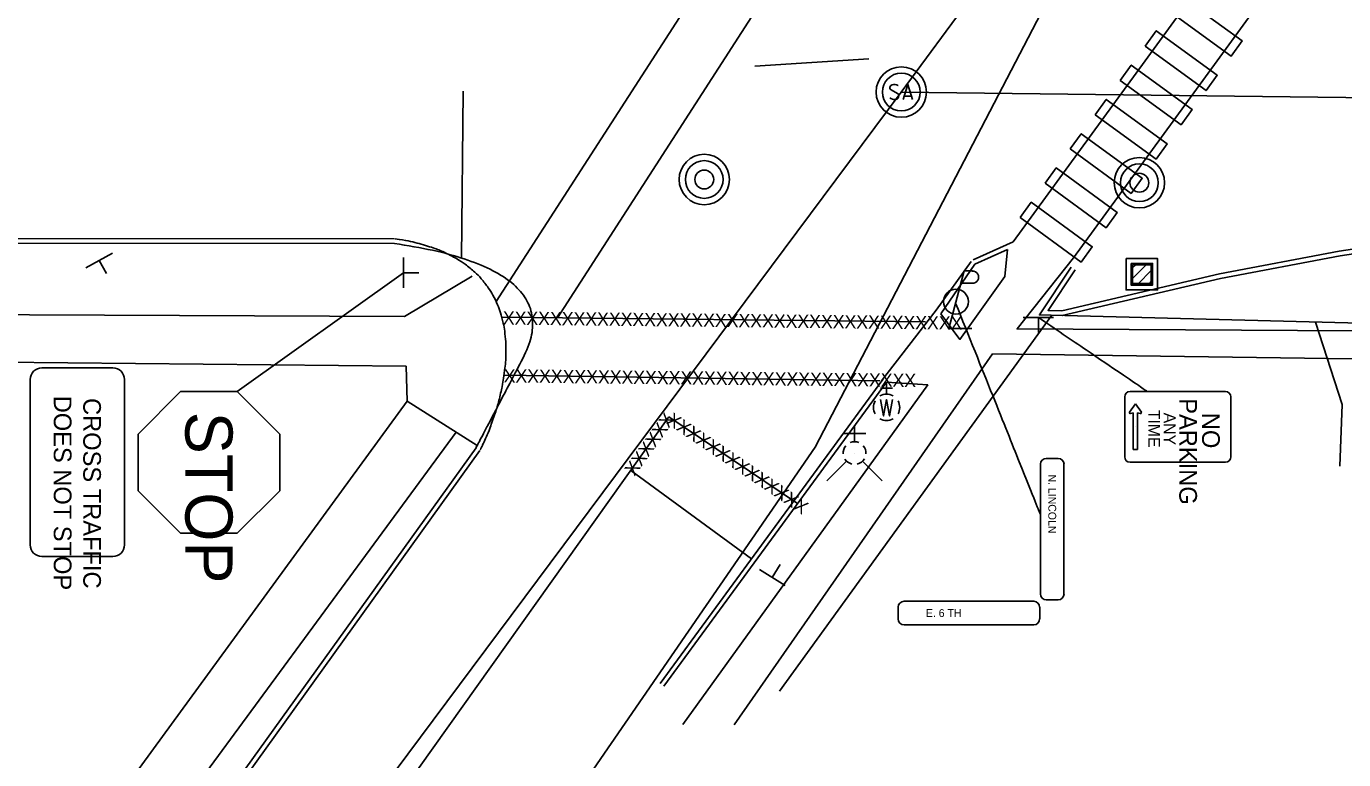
# Model space of a CAD drawing. Extents: x 108269 to 109415, y 548506 to 548874.
# Drawn here: x 108929.7 to 109069.3, y 548635.6 to 548713.3 of the extents above; entities that cross this region are included whole.
import ezdxf

# ---------------------------------------------------------------- set-up
doc = ezdxf.new("R2010")
doc.units = 0
for name, color, linetype in [('Default', 7, 'Continuous'), ('PM_P_Crosswalk', 7, 'Continuous'), ('PM_P_Removal', 7, 'Continuous'), ('PM_P_Stop_Line', 7, 'Continuous'), ('SH_Data', 7, 'Continuous'), ('SH_Text', 7, 'Continuous'), ('SN_P_Post', 7, 'Continuous'), ('SN_P_Signs', 7, 'Continuous'), ('SN_P_Text', 7, 'Continuous'), ('SN_X_Post', 7, 'Continuous'), ('SN_X_Public', 7, 'Continuous')]:
    doc.layers.add(name, color=color, linetype=linetype)

msp = doc.modelspace()

# ---------------------------------------------------------------- linework, layer by layer
at = {"layer": 'Default'}
for p, q in [((109022.45, 548706.36), (109144.06, 548871.47)), ((109013.34, 548668.7), (109047.97, 548735.38)), ((109062.3, 548728.89), (109034.32, 548690.49)), ((109069.3, 548728.02), (109040.71, 548688.79)), ((109002.56, 548719.87), (108979.51, 548684.16)), ((109010.93, 548721.11), (108986.03, 548682.43)), ((109022.45, 548708.36), (109022.45, 548708.36)), ((108875.3, 548508.88), (109022.45, 548706.36)), ((108976.03, 548706.46), (108975.84, 548688.73)), ((109022.45, 548706.36), (109022.45, 548706.36)), ((109022.45, 548706.36), (109022.45, 548706.36)), ((109022.45, 548706.36), (109022.45, 548706.36)), ((109022.45, 548706.36), (109415.28, 548701.66)), ((109022.45, 548704.36), (109022.45, 548704.36)), ((109001.57, 548699.09), (109001.57, 548699.09)), ((109047.68, 548698.75), (109047.68, 548698.75)), ((109001.57, 548697.09), (109001.57, 548697.09)), ((109001.57, 548697.09), (109001.57, 548697.09)), ((109001.57, 548697.09), (109001.57, 548697.09)), ((109047.68, 548696.75), (109047.68, 548696.75)), ((109047.68, 548696.75), (109047.68, 548696.75)), ((109047.68, 548696.75), (109047.68, 548696.75)), ((109001.57, 548695.09), (109001.57, 548695.09)), ((109047.68, 548694.75), (109047.68, 548694.75)), ((108913.18, 548690.84), (108968.76, 548690.81)), ((108913.18, 548690.34), (108968.75, 548690.31)), ((109030.06, 548688.58), (109034.32, 548690.49)), ((109030.26, 548688.12), (109033.71, 548689.66)), ((109026.15, 548683.23), (109029.85, 548688.4)), ((109026.65, 548682.86), (109030.26, 548688.12)), ((109046.8, 548686.44), (109048.56, 548688.19)), ((109046.8, 548687.57), (109047.43, 548688.19)), ((109047.94, 548688.71), (109047.94, 548688.71)), ((109047.94, 548688.05), (109047.94, 548688.05)), ((109029.11, 548687.39), (109029.98, 548687.39)), ((109046.94, 548687.05), (109046.94, 548687.05)), ((109047.4, 548685.9), (109049.09, 548687.6)), ((109047.94, 548687.05), (109047.94, 548687.05)), ((109047.94, 548687.05), (109047.94, 548687.05)), ((109047.94, 548687.05), (109047.94, 548687.05)), ((109048.53, 548685.9), (109049.09, 548686.46)), ((109048.94, 548687.05), (109048.94, 548687.05)), ((109028.77, 548686.09), (109029.98, 548686.09)), ((109047.94, 548686.05), (109047.94, 548686.05)), ((109047.94, 548685.38), (109047.94, 548685.38)), ((108980.11, 548682.5), (109025.03, 548681.99)), ((109009.53, 548642.86), (109038.39, 548682.7)), ((109020.37, 548675.75), (109026.15, 548683.23)), ((109038.39, 548682.7), (109082.29, 548681.55)), ((108980.36, 548676.36), (109020.17, 548675.75)), ((108996.9, 548643.67), (109020.48, 548675.9)), ((108997.3, 548643.38), (109020.89, 548675.6)), ((109020.89, 548674.33), (109020.89, 548675.6)), ((109021.52, 548674.97), (109020.25, 548674.97)), ((108911.44, 548593.24), (108970.1, 548673.58)), ((109020.89, 548672.93), (109020.89, 548672.93)), ((108997.83, 548671.92), (108931.45, 548578.74)), ((108997.83, 548671.92), (109011.46, 548662.73)), ((109017.5, 548669.29), (109017.5, 548671.01)), ((108916.2, 548589.93), (108975.28, 548670.32)), ((109018.7, 548670.15), (109016.3, 548670.15)), ((108977.39, 548668.66), (108921.03, 548590.17)), ((108977.8, 548668.37), (108921.44, 548589.88)), ((108930.39, 548548.27), (109013.34, 548668.7)), ((109016.65, 548667.24), (109014.57, 548665.16)), ((109017.5, 548668.09), (109017.5, 548668.09)), ((109017.5, 548668.09), (109017.5, 548668.09)), ((109018.35, 548667.24), (109020.43, 548665.16))]:
    msp.add_line(p, q, dxfattribs=at)
for points in [[(109022.11, 548707.05), (109022.09, 548707.07), (109022.05, 548707.1), (109021.94, 548707.14), (109021.8, 548707.16), (109021.7, 548707.16), (109021.66, 548707.16), (109021.5, 548707.12), (109021.36, 548707.05), (109021.27, 548706.95), (109021.25, 548706.85), (109021.25, 548706.77), (109021.27, 548706.67), (109021.37, 548706.58), (109022.06, 548706.21), (109022.13, 548706.16), (109022.15, 548706.1), (109022.18, 548706.03), (109022.18, 548705.95), (109022.16, 548705.88), (109022.15, 548705.83), (109022.13, 548705.76), (109022.1, 548705.71), (109022.08, 548705.68), (109022.04, 548705.64), (109022, 548705.61), (109021.95, 548705.59), (109021.91, 548705.58), (109021.8, 548705.56), (109021.62, 548705.56), (109021.51, 548705.59), (109021.35, 548705.68), (109021.25, 548705.75)], [(109022.66, 548705.56), (109023.16, 548707.16), (109023.65, 548705.56)], [(109023.53, 548705.94), (109022.78, 548705.94)], [(109089.48, 548690.87), (109079.37, 548690.91), (109075.22, 548690.46), (109068.87, 548689.49), (109056.19, 548687.1), (109039.46, 548683.17), (109038, 548683.21), (109040.86, 548687.51)], [(109026.65, 548682.86), (109028.67, 548680.13), (109033.41, 548686.79), (109033.71, 548689.66)], [(109040.44, 548687.78), (109037.09, 548682.73), (109039.51, 548682.67), (109056.29, 548686.61), (109068.96, 548688.99), (109075.29, 548689.96), (109079.4, 548690.41), (109089.48, 548690.37)], [(109094.15, 548680.9), (109034.73, 548681.25), (109040.71, 548688.79)], [(108898.24, 548682.87), (108969.79, 548682.57), (108976.97, 548686.84)], [(109029.11, 548687.39), (109027.48, 548681.29), (109029.92, 548681.29)], [(109066.33, 548681.97), (109069.16, 548673.22), (109068.91, 548666.69)], [(108898.23, 548677.99), (108969.97, 548677.3), (108970.1, 548673.58), (108977.51, 548668.9)], [(109169.39, 548676.69), (109032.13, 548678.6), (109004.75, 548639.27)], [(108999.31, 548639.32), (109025.26, 548675.31), (109020.89, 548675.6)], [(109020.25, 548673.75), (109020.57, 548672.03), (109020.89, 548673.75), (109021.21, 548672.03), (109021.52, 548673.75)]]:
    msp.add_lwpolyline(points, dxfattribs=at)
for points in [[(109046.28, 548688.71), (109049.61, 548688.71), (109049.61, 548685.38), (109046.28, 548685.38)], [(109046.8, 548688.19), (109049.09, 548688.19), (109049.09, 548685.9), (109046.8, 548685.9)], [(109046.94, 548688.05), (109048.94, 548688.05), (109048.94, 548686.05), (109046.94, 548686.05)]]:
    msp.add_lwpolyline(points, close=True, dxfattribs=at)
for centre, radius in [((109022.45, 548706.36), 2.67), ((109022.45, 548706.36), 2), ((109022.45, 548706.36), 2), ((109001.57, 548697.09), 2.67), ((109001.57, 548697.09), 2), ((109001.57, 548697.09), 2), ((109047.68, 548696.75), 2.67), ((109001.57, 548697.09), 1), ((109047.68, 548696.75), 2), ((109047.68, 548696.75), 2), ((109047.68, 548696.75), 1), ((109028.24, 548684.14), 1.32)]:
    msp.add_circle(centre, radius, dxfattribs=at)
for centre, radius, start, end in [((109029.99, 548686.74), 0.648, 268.8767, 91.1233), ((109020.89, 548672.93), 1.4, 60.0184, 120.0157), ((109020.89, 548672.93), 1.4, 150.0184, 209.9816), ((109020.89, 548672.93), 1.4, 330.0184, 29.9816), ((109020.89, 548672.93), 1.4, 239.9843, 299.9816), ((109017.5, 548668.09), 1.2, 140.021, 184.0629), ((109017.5, 548668.09), 1.2, 68.1395, 112.038), ((109017.5, 548668.09), 1.2, 356.0165, 39.9889), ((109017.5, 548668.09), 1.2, 211.8788, 255.8479), ((109017.5, 548668.09), 1.2, 283.8239, 329.9097)]:
    msp.add_arc(centre, radius, start, end, dxfattribs=at)
for points, degree in [([(108968.83, 548690.81), (108970.01, 548690.63), (108971.08, 548690.39), (108973.03, 548689.8), (108973.9, 548689.45), (108975.46, 548688.64), (108976.15, 548688.19), (108977.36, 548687.2), (108977.88, 548686.67), (108978.77, 548685.53), (108979.14, 548684.94), (108979.73, 548683.7), (108979.96, 548683.06), (108980.3, 548681.77), (108980.42, 548681.11), (108980.55, 548679.8), (108980.57, 548679.14), (108980.53, 548677.83), (108980.47, 548677.19), (108980.3, 548675.93), (108980.19, 548675.32), (108979.8, 548673.55), (108979.47, 548672.46), (108978.82, 548670.61), (108978.5, 548669.84), (108978.13, 548669.03), (108978.03, 548668.82), (108977.92, 548668.6), (108977.89, 548668.54), (108977.86, 548668.48), (108977.85, 548668.46), (108977.84, 548668.45), (108977.84, 548668.44), (108977.84, 548668.44), (108977.84, 548668.44), (108977.84, 548668.43), (108977.84, 548668.43), (108977.84, 548668.43)], 3), ([(108968.75, 548690.31), (108987.3, 548687.59), (108977.39, 548668.66), (108977.39, 548668.66)], 2)]:
    msp.add_open_spline(points, degree=degree, dxfattribs=at)
at = {"layer": 'PM_P_Crosswalk'}
for points in [[(109050.94, 548714.87), (109052.12, 548716.49), (109058.58, 548711.78), (109057.4, 548710.16)], [(109048.29, 548711.24), (109049.47, 548712.85), (109055.93, 548708.14), (109054.75, 548706.52)], [(109045.64, 548707.6), (109046.82, 548709.22), (109053.28, 548704.5), (109052.1, 548702.89)], [(109042.99, 548703.96), (109044.17, 548705.58), (109050.63, 548700.87), (109049.45, 548699.25)], [(109040.34, 548700.33), (109041.52, 548701.94), (109047.98, 548697.23), (109046.8, 548695.61)], [(109037.69, 548696.69), (109038.87, 548698.31), (109045.33, 548693.59), (109044.15, 548691.98)], [(109035.04, 548693.05), (109036.22, 548694.67), (109042.68, 548689.96), (109041.5, 548688.34)]]:
    msp.add_lwpolyline(points, close=True, dxfattribs=at)
at = {"layer": 'PM_P_Removal'}
msp.add_line((109006.94, 548709.12), (109019, 548709.87), dxfattribs=at)
at = {"layer": 'PM_P_Stop_Line'}
msp.add_line((108993.79, 548666.25), (109006.57, 548656.89), dxfattribs=at)
at = {"layer": 'SH_Data'}
for points in [[(109028.21, 548683.99), (109037.19, 548661.57), (109037.19, 548661.57), (109037.19, 548661.57)], [(109036.98, 548682.47), (109048.52, 548674.62), (109048.52, 548674.62), (109048.52, 548674.62)]]:
    msp.add_open_spline(points, degree=2, dxfattribs=at)
at = {"layer": 'SH_Text'}
msp.add_line((108952.08, 548674.6), (108969.71, 548687.21), dxfattribs=at)
at = {"layer": 'SN_P_Post'}
for p, q in [((108969.71, 548685.61), (108969.71, 548688.81)), ((108969.71, 548687.21), (108971.31, 548687.21)), ((108969.71, 548687.21), (108969.71, 548687.21)), ((109010.14, 548654.06), (109007.43, 548655.76)), ((109008.78, 548654.91), (109009.63, 548656.26)), ((109008.78, 548654.91), (109008.78, 548654.91))]:
    msp.add_line(p, q, dxfattribs=at)
at = {"layer": 'SN_P_Signs'}
for p, q in [((108946.08, 548674.6), (108941.58, 548670.1)), ((108952.08, 548674.6), (108946.08, 548674.6)), ((108956.58, 548670.1), (108952.08, 548674.6)), ((108941.58, 548670.1), (108941.58, 548664.1)), ((108956.58, 548664.1), (108956.58, 548670.1)), ((108941.58, 548664.1), (108946.08, 548659.6)), ((108952.08, 548659.6), (108956.58, 548664.1)), ((108946.08, 548659.6), (108952.08, 548659.6))]:
    msp.add_line(p, q, dxfattribs=at)
for points in [[(108938.89, 548677.12), (108931.39, 548677.12)], [(108930.14, 548675.87), (108930.14, 548658.37)], [(108940.14, 548658.37), (108940.14, 548675.87)], [(108931.39, 548657.12), (108938.89, 548657.12)]]:
    msp.add_lwpolyline(points, dxfattribs=at)
for centre, start, end in [((108931.39, 548675.87), 90, 180), ((108938.89, 548675.87), 0, 90), ((108931.39, 548658.37), 180, 270), ((108938.89, 548658.37), 270, 0)]:
    msp.add_arc(centre, 1.25, start, end, dxfattribs=at)
at = {"layer": 'SN_X_Post'}
for p, q in [((108936.05, 548687.73), (108938.85, 548689.28)), ((108937.45, 548688.51), (108938.22, 548687.11)), ((108937.45, 548688.51), (108937.45, 548688.51)), ((109035.38, 548682.47), (109038.58, 548682.47)), ((109036.98, 548682.47), (109036.98, 548680.87)), ((109036.98, 548682.47), (109036.98, 548682.47))]:
    msp.add_line(p, q, dxfattribs=at)
at = {"layer": 'SN_X_Public'}
for p, q in [((109047.26, 548673.3), (109046.64, 548672.42)), ((109046.75, 548672.28), (109047.03, 548672.37)), ((109047.03, 548672.37), (109047.03, 548672.36)), ((109047.03, 548672.36), (109047.03, 548668.46)), ((109047.89, 548672.42), (109047.26, 548673.3)), ((109047.5, 548672.37), (109047.78, 548672.28)), ((109047.26, 548670.88), (109047.26, 548670.88)), ((109047.03, 548668.46), (109047.5, 548668.46))]:
    msp.add_line(p, q, dxfattribs=at)
for points in [[(109046.13, 548674.05), (109046.13, 548667.68)], [(109056.81, 548674.62), (109046.69, 548674.62)], [(109057.38, 548667.68), (109057.38, 548674.05)], [(109047.5, 548668.46), (109047.5, 548672.36)], [(109037.19, 548666.9), (109037.19, 548653.15)], [(109039.07, 548667.52), (109037.82, 548667.52)], [(109039.69, 548653.15), (109039.69, 548666.9)], [(109046.69, 548667.12), (109056.81, 548667.12)], [(109022.12, 548651.75), (109022.12, 548650.5)], [(109036.49, 548652.38), (109022.74, 548652.38)], [(109037.12, 548650.5), (109037.12, 548651.75)], [(109037.82, 548652.52), (109039.07, 548652.52)], [(109022.74, 548649.88), (109036.49, 548649.88)]]:
    msp.add_lwpolyline(points, dxfattribs=at)
for centre, radius, start, end in [((109046.69, 548674.05), 0.562, 90, 180), ((109056.81, 548674.05), 0.562, 360, 90), ((109046.72, 548672.36), 0.0912, 144.9207, 287.6378), ((109047.81, 548672.36), 0.0912, 252.3622, 35.0792), ((109037.82, 548666.9), 0.625, 90, 180), ((109039.07, 548666.9), 0.625, 0, 90), ((109046.69, 548667.68), 0.562, 180, 270), ((109056.81, 548667.68), 0.562, 270, 360), ((109037.82, 548653.15), 0.625, 180, 270), ((109039.07, 548653.15), 0.625, 270, 360), ((109022.74, 548651.75), 0.625, 90, 180), ((109036.49, 548651.75), 0.625, 0, 90), ((109022.74, 548650.5), 0.625, 180, 270), ((109036.49, 548650.5), 0.625, 270, 0)]:
    msp.add_arc(centre, radius, start, end, dxfattribs=at)

# ---------------------------------------------------------------- texts
at = {"layer": 'PM_P_Removal'}
msp.add_text('XXXXXXXXXXXXXXXXXXXXXXXXXXXXXXXXXXXXXXX', height=1.4, rotation=359.3615, dxfattribs=at).set_placement((108980.22, 548681.71))
at = {"layer": 'SN_P_Signs'}
for s, height, p in [('DOES NOT STOP', 1.875, (108932.64, 548674.17)), ('CROSS TRAFFIC', 1.875, (108935.76, 548673.92)), ('STOP', 5, (108946.58, 548672.47))]:
    msp.add_text(s, height=height, rotation=270, dxfattribs=at).set_placement(p)
at = {"layer": 'SN_P_Text'}
for s, rotation, p in [('XXXXXXXXXXXXXXXXXXXXXXXXXXXXXXXXXXX', 359.3615, (108980.31, 548675.58)), ('XXXXXX', 54.5365, (108994.17, 548665.57)), ('XXXXXXXXXXXXXX', 325.9975, (108997.47, 548671.3))]:
    msp.add_text(s, height=1.4, rotation=rotation, dxfattribs=at).set_placement(p)
at = {"layer": 'SN_X_Public'}
for s, height, p in [('TIME', 1.25, (109048.63, 548672.67)), ('ANY', 1.25, (109050.27, 548672.37)), ('PARKING', 1.875, (109051.91, 548673.9)), ('NO', 1.875, (109054.33, 548672.35)), ('N. LINCOLN', 0.833, (109038.03, 548665.82))]:
    msp.add_text(s, height=height, rotation=270, dxfattribs=at).set_placement(p)
msp.add_text('E. 6 TH', height=0.833, dxfattribs=at).set_placement((109025.06, 548650.71))

doc.saveas('drawing.dxf')
